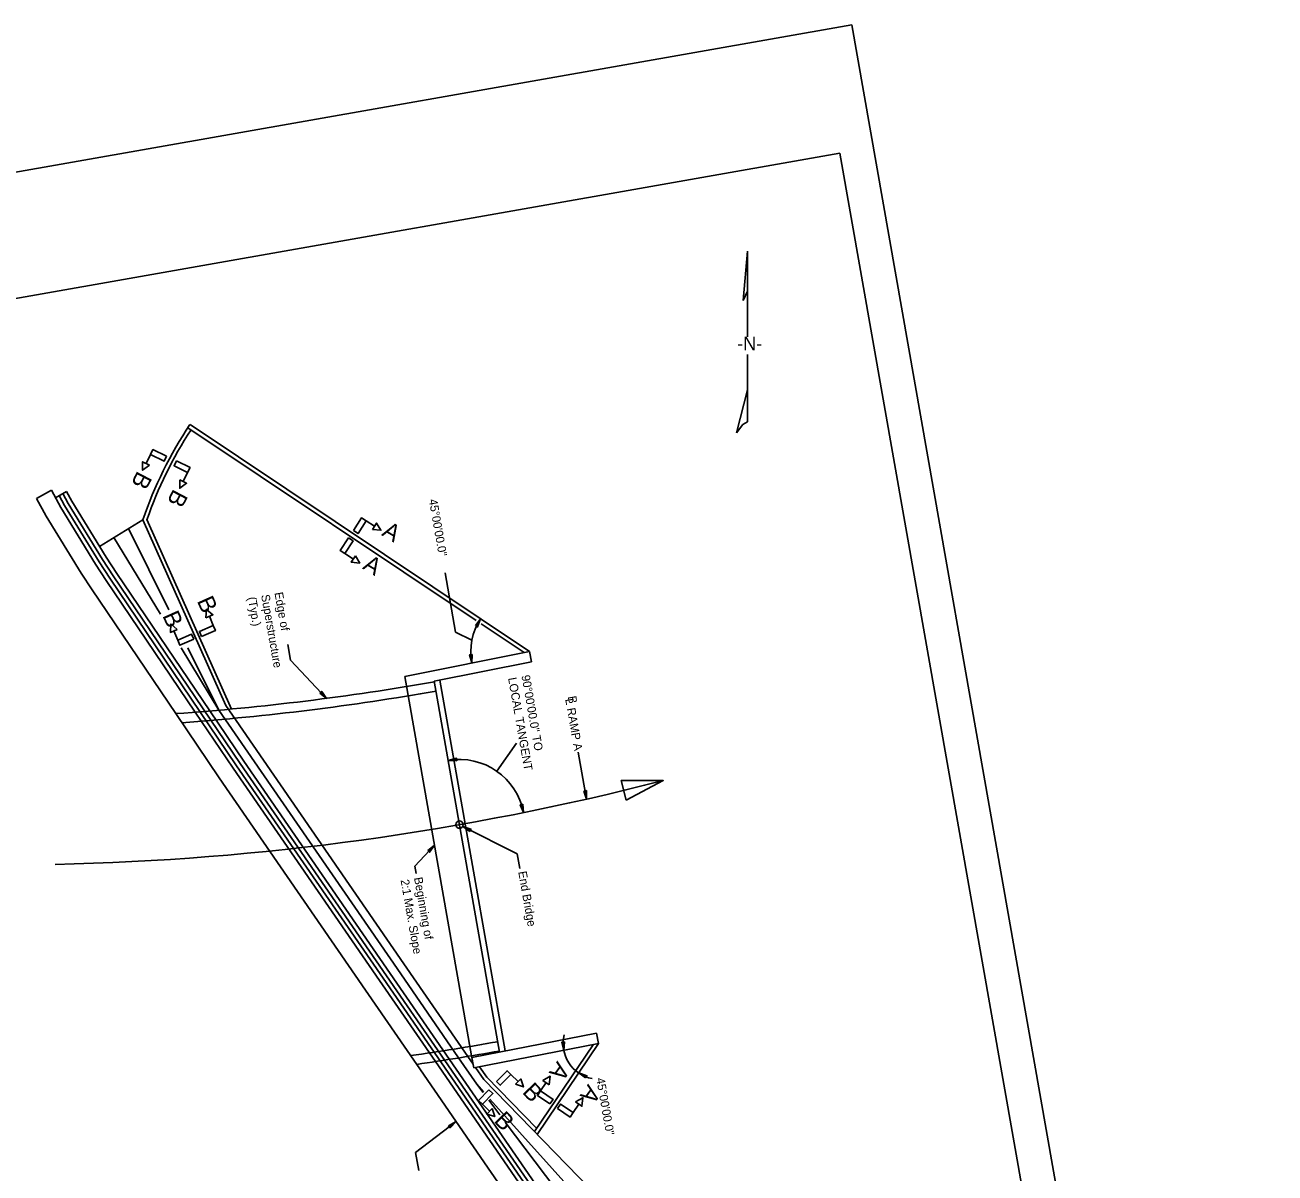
# Model space of a CAD drawing. Extents: x 1971280 to 1971503, y 796034 to 796348.
# Drawn here: x 1971355.4 to 1971502.9, y 796212.6 to 796348.1 of the extents above; entities that cross this region are included whole.
import ezdxf

# ---------------------------------------------------------------- set-up
doc = ezdxf.new("R2010")
doc.units = 0
for name, color, linetype in [('BR_AUTO DIMENSION', 7, 'Continuous'), ('BR_BORDER LINES', 7, 'Continuous'), ('BR_CENTER LINES', 7, 'Continuous'), ('BR_CONCRETE', 7, 'Continuous'), ('BR_TABLE LINES', 7, 'Continuous'), ('BR_TEXT', 7, 'Continuous'), ('Default', 7, 'Continuous'), ('Level 31', 7, 'Continuous')]:
    doc.layers.add(name, color=color, linetype=linetype)

msp = doc.modelspace()

# ---------------------------------------------------------------- linework, layer by layer
at = {"layer": 'BR_AUTO DIMENSION'}
for p, q in [((1971406.17, 796276.43), (1971404.94, 796283.44)), ((1971408.1, 796275.51), (1971406.17, 796276.43)), ((1971386.37, 796275), (1971386.7, 796273.13)), ((1971386.7, 796273.13), (1971390.95, 796268.63)), ((1971411.02, 796260.05), (1971413.37, 796263.36)), ((1971420.65, 796262.28), (1971421.63, 796256.74)), ((1971407.03, 796253.53), (1971413.45, 796250.28)), ((1971401.38, 796248.84), (1971403.69, 796251.3)), ((1971413.45, 796250.28), (1971413.75, 796248.55)), ((1971401.54, 796247.97), (1971401.38, 796248.84)), ((1971406.24, 796218.69), (1971401.46, 796215.05)), ((1971401.46, 796215.05), (1971401.84, 796212.92))]:
    msp.add_line(p, q, dxfattribs=at)
for points in [[(1971408.51, 796277.21), (1971409.13, 796278.01), (1971408.77, 796277.06)], [(1971408.12, 796273.82), (1971408.1, 796272.81), (1971407.82, 796273.78)], [(1971390.16, 796269.26), (1971390.95, 796268.63), (1971390.38, 796269.46)], [(1971406.32, 796261.27), (1971405.31, 796261.3), (1971406.29, 796261.56)], [(1971421.31, 796257.7), (1971421.63, 796256.74), (1971421.6, 796257.75)], [(1971414.1, 796256.16), (1971414.2, 796255.15), (1971413.81, 796256.08)], [(1971407.86, 796252.94), (1971407.03, 796253.53), (1971407.99, 796253.21)], [(1971402.89, 796250.67), (1971403.69, 796251.3), (1971403.11, 796250.47)], [(1971419.01, 796228.1), (1971418.94, 796227.1), (1971418.71, 796228.08)], [(1971421.52, 796223.84), (1971420.7, 796224.43), (1971421.66, 796224.11)], [(1971405.35, 796218.21), (1971406.24, 796218.69), (1971405.53, 796217.97)]]:
    msp.add_lwpolyline(points, close=True, dxfattribs=at)
msp.add_circle((1971406.64, 796253.73), 0.434, dxfattribs=at)
for centre, radius, start, end in [((1971414.89, 796274.16), 6.93, 146.237, 191.237), ((1971406.64, 796253.73), 7.69, 10.6888, 99.987), ((1971423.04, 796227.89), 4.18, 165.7538, 259.6923)]:
    msp.add_arc(centre, radius, start, end, dxfattribs=at)
at = {"layer": 'BR_BORDER LINES'}
for p in [(1971286.06, 796303.81), (1971498.22, 796067.69)]:
    msp.add_line(p, (1971451.51, 796332.94), dxfattribs=at)
at = {"layer": 'BR_CENTER LINES'}
msp.add_arc((1971352.19, 796562.97), 314, 271.2269, 284.4737, dxfattribs=at)
at = {"layer": 'BR_CONCRETE'}
for p, q in [((1971408.61, 796277.82), (1971374.59, 796300.56)), ((1971414.89, 796274.16), (1971374.84, 796300.93)), ((1971358.49, 796293.18), (1971356.73, 796292.22)), ((1971360.28, 796293.03), (1971358.97, 796292.31)), ((1971369.28, 796289.69), (1971364.16, 796286.56)), ((1971372.34, 796279.09), (1971367.6, 796288.61)), ((1971379.08, 796267.79), (1971369.28, 796289.69)), ((1971379.75, 796267.37), (1971369.76, 796289.72)), ((1971371.36, 796278.56), (1971365.86, 796287.6)), ((1971414.28, 796274.04), (1971409.21, 796277.42)), ((1971378.25, 796267.24), (1971373.78, 796274.58)), ((1971378.25, 796267.24), (1971374.59, 796274.58)), ((1971414.89, 796274.16), (1971400.18, 796271.23)), ((1971414.89, 796274.16), (1971415.13, 796272.93)), ((1971415.13, 796272.93), (1971403.66, 796270.65)), ((1971400.18, 796271.23), (1971408.06, 796226.45)), ((1971404.32, 796270.78), (1971412.02, 796227.03)), ((1971403.66, 796270.65), (1971411.37, 796226.9)), ((1971422.8, 796229.12), (1971408.1, 796226.26)), ((1971423.04, 796227.89), (1971422.8, 796229.12)), ((1971423.04, 796227.89), (1971408.31, 796225.03)), ((1971422.42, 796227.77), (1971415.5, 796217.51)), ((1971423.04, 796227.89), (1971415.81, 796217.18)), ((1971408.67, 796223.1), (1971406.53, 796226.2)), ((1971408.23, 796225.49), (1971407.62, 796226.38)), ((1971408.06, 796226.45), (1971408.31, 796225.03)), ((1971409, 796225.16), (1971409.86, 796223.92)), ((1971409.49, 796223.66), (1971426.19, 796206.54)), ((1971409.81, 796223.97), (1971415.75, 796217.88)), ((1971408.67, 796223.1), (1971409.47, 796222.2)), ((1971408.67, 796223.1), (1971409.41, 796222.12)), ((1971410.1, 796221.21), (1971411.38, 796219.51)), ((1971410.23, 796221.36), (1971424.55, 796205.4)), ((1971412.04, 796218.64), (1971422.92, 796204.25))]:
    msp.add_line(p, q, dxfattribs=at)
for points in [[(1971358.49, 796293.18), (1971359.61, 796291.14), (1971363.68, 796284.48), (1971364.94, 796282.55), (1971375.46, 796267.01)], [(1971360.28, 796293.03), (1971360.91, 796291.89), (1971364.95, 796285.28), (1971366.19, 796283.38), (1971377.17, 796267.15)], [(1971356.73, 796292.22), (1971357.88, 796290.13), (1971361.99, 796283.41), (1971363.28, 796281.44), (1971373.16, 796266.83)], [(1971359.41, 796292.55), (1971360.04, 796291.39), (1971364.1, 796284.75), (1971365.36, 796282.83), (1971380.34, 796260.67), (1971397.61, 796235.61), (1971417.05, 796207.42), (1971442.19, 796171.41)], [(1971359.85, 796292.79), (1971360.47, 796291.64), (1971364.52, 796285.01), (1971365.78, 796283.1), (1971380.75, 796260.96), (1971398.02, 796235.9), (1971417.46, 796207.7), (1971442.6, 796171.7)], [(1971373.16, 796266.83), (1971378.28, 796259.26), (1971395.55, 796234.19), (1971401.59, 796225.44)], [(1971375.46, 796267.01), (1971379.93, 796260.39), (1971397.2, 796235.33), (1971403.79, 796225.77)], [(1971377.17, 796267.15), (1971381.17, 796261.24), (1971398.44, 796236.18), (1971405.44, 796226.02)], [(1971378.25, 796267.24), (1971399.26, 796236.75), (1971406.53, 796226.2)], [(1971379.07, 796267.8), (1971400.08, 796237.32), (1971407.62, 796226.38)], [(1971401.59, 796225.44), (1971414.99, 796205.99), (1971440.14, 796169.98)], [(1971403.79, 796225.77), (1971416.64, 796207.13), (1971441.78, 796171.12)], [(1971405.44, 796226.02), (1971417.87, 796207.99), (1971443.01, 796171.98)], [(1971408.52, 796225.07), (1971409.49, 796223.66)]]:
    msp.add_lwpolyline(points, dxfattribs=at)
for centre, radius, start, end in [((1971414.89, 796274.13), 48.2, 146.216, 161.1624), ((1971414.89, 796274.13), 47.75, 146.7472, 160.9539), ((1971352.19, 796562.97), 296.88, 274.05, 279.987), ((1971352.19, 796562.97), 298, 274.1749, 279.987), ((1971352.19, 796562.97), 340, 278.233, 279.987), ((1971352.19, 796562.97), 341.12, 278.3265, 279.987)]:
    msp.add_arc(centre, radius, start, end, dxfattribs=at)
at = {"layer": 'BR_TABLE LINES'}
for p, q in [((1971370.18, 796297.4), (1971369.65, 796296.34)), ((1971374.55, 796295.28), (1971374.03, 796294.22)), ((1971395.62, 796289.58), (1971396.62, 796288.94)), ((1971393.11, 796285.71), (1971394.11, 796285.07)), ((1971377.58, 796277.22), (1971377.12, 796278.32)), ((1971373.39, 796275.51), (1971372.93, 796276.6)), ((1971412.7, 796224.24), (1971413.55, 796223.41)), ((1971416.19, 796222.31), (1971416.85, 796223.3)), ((1971409.33, 796220.74), (1971410.17, 796219.91)), ((1971420.04, 796219.77), (1971420.7, 796220.76))]:
    msp.add_line(p, q, dxfattribs=at)
for points in [[(1971372.06, 796297.19), (1971371.77, 796296.61), (1971370.18, 796297.4), (1971370.47, 796297.98)], [(1971370.05, 796296.14), (1971369.25, 796295.54), (1971369.25, 796296.54)], [(1971373.25, 796296.65), (1971372.96, 796296.07), (1971374.55, 796295.28), (1971374.84, 796295.86)], [(1971373.63, 796294.42), (1971373.63, 796293.42), (1971374.43, 796294.02)], [(1971394.11, 796288.43), (1971394.66, 796288.08), (1971395.62, 796289.58), (1971395.07, 796289.93)], [(1971396.38, 796288.57), (1971397.37, 796288.46), (1971396.86, 796289.32)], [(1971393.52, 796287.56), (1971394.07, 796287.21), (1971393.11, 796285.71), (1971392.56, 796286.06)], [(1971394.35, 796285.45), (1971394.86, 796284.6), (1971393.87, 796284.7)], [(1971376.71, 796278.14), (1971376.78, 796279.13), (1971377.53, 796278.49)], [(1971373.34, 796276.77), (1971372.58, 796277.42), (1971372.52, 796276.42)], [(1971376.2, 796275.93), (1971375.95, 796276.53), (1971377.58, 796277.22), (1971377.84, 796276.62)], [(1971375.28, 796275.6), (1971375.02, 796276.2), (1971373.39, 796275.51), (1971373.64, 796274.9)], [(1971410.99, 796223.43), (1971411.45, 796222.98), (1971412.7, 796224.24), (1971412.24, 796224.7)], [(1971413.23, 796223.1), (1971414.18, 796222.79), (1971413.86, 796223.73)], [(1971417.22, 796223.05), (1971417.34, 796224.04), (1971416.48, 796223.54)], [(1971410.11, 796222.46), (1971410.57, 796222.01), (1971409.33, 796220.74), (1971408.86, 796221.19)], [(1971417.31, 796220.78), (1971417.67, 796221.32), (1971416.19, 796222.31), (1971415.83, 796221.77)], [(1971418.2, 796220.22), (1971418.56, 796220.76), (1971420.04, 796219.77), (1971419.68, 796219.23)], [(1971420.33, 796221.01), (1971421.19, 796221.5), (1971421.07, 796220.51)], [(1971410.48, 796220.22), (1971410.8, 796219.29), (1971409.86, 796219.59)]]:
    msp.add_lwpolyline(points, close=True, dxfattribs=at)
at = {"layer": 'BR_TEXT'}
for p, q in [((1971440.1, 796315.59), (1971440.63, 796321.41)), ((1971440.63, 796321.41), (1971440.63, 796311.29)), ((1971440.63, 796321.41), (1971440.63, 796316.67)), ((1971440.63, 796316.67), (1971440.1, 796315.59)), ((1971440.63, 796309.2), (1971440.63, 796301.25)), ((1971439.31, 796299.97), (1971440.63, 796305.05)), ((1971440.63, 796305.05), (1971440.63, 796304.42)), ((1971440.63, 796304.42), (1971440.63, 796301.25))]:
    msp.add_line(p, q, dxfattribs=at)
msp.add_lwpolyline([(1971440.63, 796301.25), (1971440.06, 796300.94), (1971439.31, 796299.97)], dxfattribs=at)
at = {"layer": 'Default'}
msp.add_lwpolyline([(1971426.3, 796256.6), (1971430.67, 796258.93), (1971425.72, 796258.93)], close=True, dxfattribs=at)
at = {"layer": 'Level 31'}
for p, q in [((1971452.91, 796348.08), (1971279.58, 796317.56)), ((1971502.85, 796064.44), (1971452.91, 796348.08))]:
    msp.add_line(p, q, dxfattribs=at)

# ---------------------------------------------------------------- texts
at = {"layer": 'BR_TEXT'}
for s, height, rotation, p in [('-N-', 1.6, 360, (1971439.39, 796309.7)), ('B', 2, 242.3978, (1971368.66, 796295.56)), ('B', 2, 242.3978, (1971372.9, 796293.43)), ('45%%D00\'00.0"', 0.9998, 279.987, (1971403.01, 796292.06)), ('A', 2, 329.3366, (1971397.36, 796287.91)), ('A', 2, 329.3366, (1971395.11, 796283.97)), ('Edge of', 1, 279.987, (1971384.8, 796281.08)), ('B', 2, 294.0726, (1971375.62, 796280.14)), ('(Typ.)', 1, 279.987, (1971381.65, 796280.52)), ('Superstructure', 1, 279.987, (1971383.22, 796280.8)), ('B', 2, 294.0726, (1971371.55, 796278.4)), ('LOCAL TANGENT', 0.9998, 279.987, (1971412.36, 796271.02)), ('90%%D00\'00.0" TO ', 0.9998, 279.987, (1971413.94, 796271.3)), ('L RAMP A', 1, 279.987, (1971419.1, 796268.53)), ('B', 1, 279.987, (1971419.41, 796268.83)), ('2:1 Max. Slope', 1, 279.987, (1971399.68, 796247.18)), ('Beginning of', 1, 279.987, (1971401.26, 796247.45)), ('End Bridge', 1, 279.987, (1971413.56, 796248.16)), ('A', 2, 234.2628, (1971418.18, 796225.9)), ('45%%D00\'00.0"', 0.9998, 279.987, (1971422.76, 796223.77)), ('B', 2, 314.3192, (1971413.95, 796222.1)), ('A', 2, 234.2628, (1971421.82, 796223.19)), ('B', 2, 314.3192, (1971410.6, 796218.72))]:
    msp.add_text(s, height=height, rotation=rotation, dxfattribs=at).set_placement(p)

doc.saveas('drawing.dxf')
